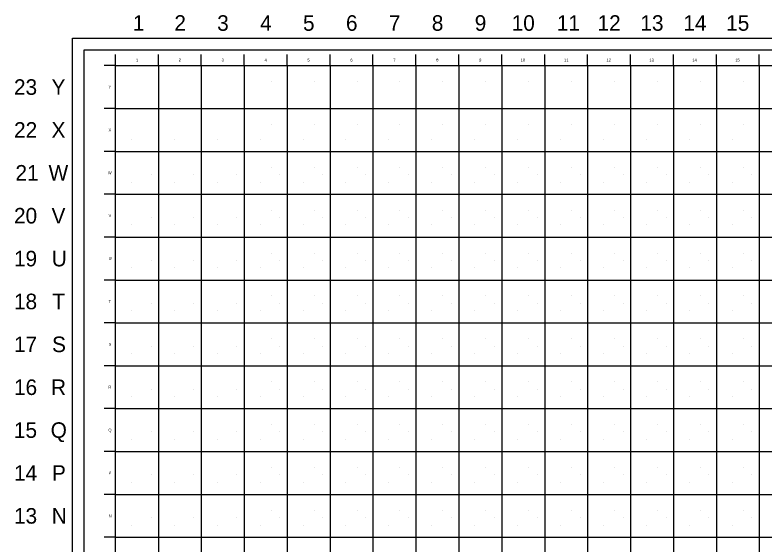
# Model space of a CAD drawing. Extents: x -0.05 to 1.19, y 0 to 0.86.
# Drawn here: x -0.047 to 0.565, y 0.428 to 0.86 of the extents above; entities that cross this region are included whole.
import ezdxf

# ---------------------------------------------------------------- set-up
doc = ezdxf.new("R2010")
doc.units = 0
for name, color, linetype in [('G-ANNO-NPLT', 7, 'Continuous'), ('G-ANNO-TEXT', 7, 'Continuous'), ('G-ANNO-TTLB', 7, 'Continuous'), ('G-ANNO-TTLB-GRID', 7, 'Continuous')]:
    doc.layers.add(name, color=color, linetype=linetype)

msp = doc.modelspace()

# ---------------------------------------------------------------- linework, layer by layer
at = {"layer": 'G-ANNO-NPLT'}
for p, q in [((0.16207, 0.80547), (0.16207, 0.80547)), ((0.19708, 0.80547), (0.19708, 0.80547)), ((0.23207, 0.80547), (0.23207, 0.80547)), ((0.26708, 0.80547), (0.26708, 0.80547)), ((0.30207, 0.80547), (0.30207, 0.80547)), ((0.33707, 0.80547), (0.33707, 0.80547)), ((0.37207, 0.80547), (0.37207, 0.80547)), ((0.40707, 0.80547), (0.40707, 0.80547)), ((0.44207, 0.80547), (0.44207, 0.80547)), ((0.47707, 0.80547), (0.47707, 0.80547)), ((0.51207, 0.80547), (0.51207, 0.80547)), ((0.54707, 0.80547), (0.54707, 0.80547)), ((0.16207, 0.77047), (0.16207, 0.77047)), ((0.19708, 0.77047), (0.19708, 0.77047)), ((0.23207, 0.77047), (0.23207, 0.77047)), ((0.26708, 0.77047), (0.26708, 0.77047)), ((0.30207, 0.77047), (0.30207, 0.77047)), ((0.33707, 0.77047), (0.33707, 0.77047)), ((0.37207, 0.77047), (0.37207, 0.77047)), ((0.40707, 0.77047), (0.40707, 0.77047)), ((0.44207, 0.77047), (0.44207, 0.77047)), ((0.47707, 0.77047), (0.47707, 0.77047)), ((0.51207, 0.77047), (0.51207, 0.77047)), ((0.54707, 0.77047), (0.54707, 0.77047)), ((0.04807, 0.75847), (0.04807, 0.75847)), ((0.08307, 0.75847), (0.08307, 0.75847)), ((0.11807, 0.75847), (0.11807, 0.75847)), ((0.15307, 0.75847), (0.15307, 0.75847)), ((0.18807, 0.75847), (0.18807, 0.75847)), ((0.22307, 0.75847), (0.22307, 0.75847)), ((0.25807, 0.75847), (0.25807, 0.75847)), ((0.29307, 0.75847), (0.29307, 0.75847)), ((0.32808, 0.75847), (0.32808, 0.75847)), ((0.36307, 0.75847), (0.36307, 0.75847)), ((0.39807, 0.75847), (0.39807, 0.75847)), ((0.43307, 0.75847), (0.43307, 0.75847)), ((0.46807, 0.75847), (0.46807, 0.75847)), ((0.50307, 0.75847), (0.50307, 0.75847)), ((0.53807, 0.75847), (0.53807, 0.75847)), ((0.16207, 0.73547), (0.16207, 0.73547)), ((0.19708, 0.73547), (0.19708, 0.73547)), ((0.23207, 0.73547), (0.23207, 0.73547)), ((0.26708, 0.73547), (0.26708, 0.73547)), ((0.30207, 0.73547), (0.30207, 0.73547)), ((0.33707, 0.73547), (0.33707, 0.73547)), ((0.37207, 0.73547), (0.37207, 0.73547)), ((0.40707, 0.73547), (0.40707, 0.73547)), ((0.44207, 0.73547), (0.44207, 0.73547)), ((0.47707, 0.73547), (0.47707, 0.73547)), ((0.51207, 0.73547), (0.51207, 0.73547)), ((0.54707, 0.73547), (0.54707, 0.73547)), ((0.06407, 0.72947), (0.06407, 0.72947)), ((0.09907, 0.72947), (0.09907, 0.72947)), ((0.13407, 0.72947), (0.13407, 0.72947)), ((0.16908, 0.72947), (0.16908, 0.72947)), ((0.20407, 0.72947), (0.20407, 0.72947)), ((0.23907, 0.72947), (0.23907, 0.72947)), ((0.27408, 0.72947), (0.27408, 0.72947)), ((0.30907, 0.72947), (0.30907, 0.72947)), ((0.34407, 0.72947), (0.34407, 0.72947)), ((0.37907, 0.72947), (0.37907, 0.72947)), ((0.41407, 0.72947), (0.41407, 0.72947)), ((0.44908, 0.72947), (0.44908, 0.72947)), ((0.48407, 0.72947), (0.48407, 0.72947)), ((0.51907, 0.72947), (0.51907, 0.72947)), ((0.55407, 0.72947), (0.55407, 0.72947)), ((0.04807, 0.72347), (0.04807, 0.72347)), ((0.08307, 0.72347), (0.08307, 0.72347)), ((0.11807, 0.72347), (0.11807, 0.72347)), ((0.15307, 0.72347), (0.15307, 0.72347)), ((0.18807, 0.72347), (0.18807, 0.72347)), ((0.22307, 0.72347), (0.22307, 0.72347)), ((0.25807, 0.72347), (0.25807, 0.72347)), ((0.29307, 0.72347), (0.29307, 0.72347)), ((0.32808, 0.72347), (0.32808, 0.72347)), ((0.36307, 0.72347), (0.36307, 0.72347)), ((0.39807, 0.72347), (0.39807, 0.72347)), ((0.43307, 0.72347), (0.43307, 0.72347)), ((0.46807, 0.72347), (0.46807, 0.72347)), ((0.50307, 0.72347), (0.50307, 0.72347)), ((0.53807, 0.72347), (0.53807, 0.72347)), ((0.16207, 0.70047), (0.16207, 0.70047)), ((0.19708, 0.70047), (0.19708, 0.70047)), ((0.23207, 0.70047), (0.23207, 0.70047)), ((0.26708, 0.70047), (0.26708, 0.70047)), ((0.30207, 0.70047), (0.30207, 0.70047)), ((0.33707, 0.70047), (0.33707, 0.70047)), ((0.37207, 0.70047), (0.37207, 0.70047)), ((0.40707, 0.70047), (0.40707, 0.70047)), ((0.44207, 0.70047), (0.44207, 0.70047)), ((0.47707, 0.70047), (0.47707, 0.70047)), ((0.51207, 0.70047), (0.51207, 0.70047)), ((0.54707, 0.70047), (0.54707, 0.70047)), ((0.06407, 0.69447), (0.06407, 0.69447)), ((0.09907, 0.69447), (0.09907, 0.69447)), ((0.13407, 0.69447), (0.13407, 0.69447)), ((0.16908, 0.69447), (0.16908, 0.69447)), ((0.20407, 0.69447), (0.20407, 0.69447)), ((0.23907, 0.69447), (0.23907, 0.69447)), ((0.27408, 0.69447), (0.27408, 0.69447)), ((0.30907, 0.69447), (0.30907, 0.69447)), ((0.34407, 0.69447), (0.34407, 0.69447)), ((0.37907, 0.69447), (0.37907, 0.69447)), ((0.41407, 0.69447), (0.41407, 0.69447)), ((0.44908, 0.69447), (0.44908, 0.69447)), ((0.48407, 0.69447), (0.48407, 0.69447)), ((0.51907, 0.69447), (0.51907, 0.69447)), ((0.55407, 0.69447), (0.55407, 0.69447)), ((0.04807, 0.68847), (0.04807, 0.68847)), ((0.08307, 0.68847), (0.08307, 0.68847)), ((0.11807, 0.68847), (0.11807, 0.68847)), ((0.15307, 0.68847), (0.15307, 0.68847)), ((0.18807, 0.68847), (0.18807, 0.68847)), ((0.22307, 0.68847), (0.22307, 0.68847)), ((0.25807, 0.68847), (0.25807, 0.68847)), ((0.29307, 0.68847), (0.29307, 0.68847)), ((0.32808, 0.68847), (0.32808, 0.68847)), ((0.36307, 0.68847), (0.36307, 0.68847)), ((0.39807, 0.68847), (0.39807, 0.68847)), ((0.43307, 0.68847), (0.43307, 0.68847)), ((0.46807, 0.68847), (0.46807, 0.68847)), ((0.50307, 0.68847), (0.50307, 0.68847)), ((0.53807, 0.68847), (0.53807, 0.68847)), ((0.16207, 0.66547), (0.16207, 0.66547)), ((0.19708, 0.66547), (0.19708, 0.66547)), ((0.23207, 0.66547), (0.23207, 0.66547)), ((0.26708, 0.66547), (0.26708, 0.66547)), ((0.30207, 0.66547), (0.30207, 0.66547)), ((0.33707, 0.66547), (0.33707, 0.66547)), ((0.37207, 0.66547), (0.37207, 0.66547)), ((0.40707, 0.66547), (0.40707, 0.66547)), ((0.44207, 0.66547), (0.44207, 0.66547)), ((0.47707, 0.66547), (0.47707, 0.66547)), ((0.51207, 0.66547), (0.51207, 0.66547)), ((0.54707, 0.66547), (0.54707, 0.66547)), ((0.06407, 0.65947), (0.06407, 0.65947)), ((0.09907, 0.65947), (0.09907, 0.65947)), ((0.13407, 0.65947), (0.13407, 0.65947)), ((0.16908, 0.65947), (0.16908, 0.65947)), ((0.20407, 0.65947), (0.20407, 0.65947)), ((0.23907, 0.65947), (0.23907, 0.65947)), ((0.27408, 0.65947), (0.27408, 0.65947)), ((0.30907, 0.65947), (0.30907, 0.65947)), ((0.34407, 0.65947), (0.34407, 0.65947)), ((0.37907, 0.65947), (0.37907, 0.65947)), ((0.41407, 0.65947), (0.41407, 0.65947)), ((0.44908, 0.65947), (0.44908, 0.65947)), ((0.48407, 0.65947), (0.48407, 0.65947)), ((0.51907, 0.65947), (0.51907, 0.65947)), ((0.55407, 0.65947), (0.55407, 0.65947)), ((0.04807, 0.65347), (0.04807, 0.65347)), ((0.08307, 0.65347), (0.08307, 0.65347)), ((0.11807, 0.65347), (0.11807, 0.65347)), ((0.15307, 0.65347), (0.15307, 0.65347)), ((0.18807, 0.65347), (0.18807, 0.65347)), ((0.22307, 0.65347), (0.22307, 0.65347)), ((0.25807, 0.65347), (0.25807, 0.65347)), ((0.29307, 0.65347), (0.29307, 0.65347)), ((0.32808, 0.65347), (0.32808, 0.65347)), ((0.36307, 0.65347), (0.36307, 0.65347)), ((0.39807, 0.65347), (0.39807, 0.65347)), ((0.43307, 0.65347), (0.43307, 0.65347)), ((0.46807, 0.65347), (0.46807, 0.65347)), ((0.50307, 0.65347), (0.50307, 0.65347)), ((0.53807, 0.65347), (0.53807, 0.65347)), ((0.16207, 0.63047), (0.16207, 0.63047)), ((0.19708, 0.63047), (0.19708, 0.63047)), ((0.23207, 0.63047), (0.23207, 0.63047)), ((0.26708, 0.63047), (0.26708, 0.63047)), ((0.30207, 0.63047), (0.30207, 0.63047)), ((0.33707, 0.63047), (0.33707, 0.63047)), ((0.37207, 0.63047), (0.37207, 0.63047)), ((0.40707, 0.63047), (0.40707, 0.63047)), ((0.44207, 0.63047), (0.44207, 0.63047)), ((0.47707, 0.63047), (0.47707, 0.63047)), ((0.51207, 0.63047), (0.51207, 0.63047)), ((0.54707, 0.63047), (0.54707, 0.63047)), ((0.06407, 0.62447), (0.06407, 0.62447)), ((0.09907, 0.62447), (0.09907, 0.62447)), ((0.13407, 0.62447), (0.13407, 0.62447)), ((0.16908, 0.62447), (0.16908, 0.62447)), ((0.20407, 0.62447), (0.20407, 0.62447)), ((0.23907, 0.62447), (0.23907, 0.62447)), ((0.27408, 0.62447), (0.27408, 0.62447)), ((0.30907, 0.62447), (0.30907, 0.62447)), ((0.34407, 0.62447), (0.34407, 0.62447)), ((0.37907, 0.62447), (0.37907, 0.62447)), ((0.41407, 0.62447), (0.41407, 0.62447)), ((0.44908, 0.62447), (0.44908, 0.62447)), ((0.48407, 0.62447), (0.48407, 0.62447)), ((0.51907, 0.62447), (0.51907, 0.62447)), ((0.55407, 0.62447), (0.55407, 0.62447)), ((0.04807, 0.61847), (0.04807, 0.61847)), ((0.08307, 0.61847), (0.08307, 0.61847)), ((0.11807, 0.61847), (0.11807, 0.61847)), ((0.15307, 0.61847), (0.15307, 0.61847)), ((0.18807, 0.61847), (0.18807, 0.61847)), ((0.22307, 0.61847), (0.22307, 0.61847)), ((0.25807, 0.61847), (0.25807, 0.61847)), ((0.29307, 0.61847), (0.29307, 0.61847)), ((0.32808, 0.61847), (0.32808, 0.61847)), ((0.36307, 0.61847), (0.36307, 0.61847)), ((0.39807, 0.61847), (0.39807, 0.61847)), ((0.43307, 0.61847), (0.43307, 0.61847)), ((0.46807, 0.61847), (0.46807, 0.61847)), ((0.50307, 0.61847), (0.50307, 0.61847)), ((0.53807, 0.61847), (0.53807, 0.61847)), ((0.16207, 0.59547), (0.16207, 0.59547)), ((0.19708, 0.59547), (0.19708, 0.59547)), ((0.23207, 0.59547), (0.23207, 0.59547)), ((0.26708, 0.59547), (0.26708, 0.59547)), ((0.30207, 0.59547), (0.30207, 0.59547)), ((0.33707, 0.59547), (0.33707, 0.59547)), ((0.37207, 0.59547), (0.37207, 0.59547)), ((0.40707, 0.59547), (0.40707, 0.59547)), ((0.44207, 0.59547), (0.44207, 0.59547)), ((0.47707, 0.59547), (0.47707, 0.59547)), ((0.51207, 0.59547), (0.51207, 0.59547)), ((0.54707, 0.59547), (0.54707, 0.59547)), ((0.06407, 0.58947), (0.06407, 0.58947)), ((0.09907, 0.58947), (0.09907, 0.58947)), ((0.13407, 0.58947), (0.13407, 0.58947)), ((0.16908, 0.58947), (0.16908, 0.58947)), ((0.20407, 0.58947), (0.20407, 0.58947)), ((0.23907, 0.58947), (0.23907, 0.58947)), ((0.27408, 0.58947), (0.27408, 0.58947)), ((0.30907, 0.58947), (0.30907, 0.58947)), ((0.34407, 0.58947), (0.34407, 0.58947)), ((0.37907, 0.58947), (0.37907, 0.58947)), ((0.41407, 0.58947), (0.41407, 0.58947)), ((0.44908, 0.58947), (0.44908, 0.58947)), ((0.48407, 0.58947), (0.48407, 0.58947)), ((0.51907, 0.58947), (0.51907, 0.58947)), ((0.55407, 0.58947), (0.55407, 0.58947)), ((0.04807, 0.58347), (0.04807, 0.58347)), ((0.08307, 0.58347), (0.08307, 0.58347)), ((0.11807, 0.58347), (0.11807, 0.58347)), ((0.15307, 0.58347), (0.15307, 0.58347)), ((0.18807, 0.58347), (0.18807, 0.58347)), ((0.22307, 0.58347), (0.22307, 0.58347)), ((0.25807, 0.58347), (0.25807, 0.58347)), ((0.29307, 0.58347), (0.29307, 0.58347)), ((0.32808, 0.58347), (0.32808, 0.58347)), ((0.36307, 0.58347), (0.36307, 0.58347)), ((0.39807, 0.58347), (0.39807, 0.58347)), ((0.43307, 0.58347), (0.43307, 0.58347)), ((0.46807, 0.58347), (0.46807, 0.58347)), ((0.50307, 0.58347), (0.50307, 0.58347)), ((0.53807, 0.58347), (0.53807, 0.58347)), ((0.16207, 0.56047), (0.16207, 0.56047)), ((0.19708, 0.56047), (0.19708, 0.56047)), ((0.23207, 0.56047), (0.23207, 0.56047)), ((0.26708, 0.56047), (0.26708, 0.56047)), ((0.30207, 0.56047), (0.30207, 0.56047)), ((0.33707, 0.56047), (0.33707, 0.56047)), ((0.37207, 0.56047), (0.37207, 0.56047)), ((0.40707, 0.56047), (0.40707, 0.56047)), ((0.44207, 0.56047), (0.44207, 0.56047)), ((0.47707, 0.56047), (0.47707, 0.56047)), ((0.51207, 0.56047), (0.51207, 0.56047)), ((0.54707, 0.56047), (0.54707, 0.56047)), ((0.06407, 0.55447), (0.06407, 0.55447)), ((0.09907, 0.55447), (0.09907, 0.55447)), ((0.13407, 0.55447), (0.13407, 0.55447)), ((0.16908, 0.55447), (0.16908, 0.55447)), ((0.20407, 0.55447), (0.20407, 0.55447)), ((0.23907, 0.55447), (0.23907, 0.55447)), ((0.27408, 0.55447), (0.27408, 0.55447)), ((0.30907, 0.55447), (0.30907, 0.55447)), ((0.34407, 0.55447), (0.34407, 0.55447)), ((0.37907, 0.55447), (0.37907, 0.55447)), ((0.41407, 0.55447), (0.41407, 0.55447)), ((0.44908, 0.55447), (0.44908, 0.55447)), ((0.48407, 0.55447), (0.48407, 0.55447)), ((0.51907, 0.55447), (0.51907, 0.55447)), ((0.55407, 0.55447), (0.55407, 0.55447)), ((0.04807, 0.54847), (0.04807, 0.54847)), ((0.08307, 0.54847), (0.08307, 0.54847)), ((0.11807, 0.54847), (0.11807, 0.54847)), ((0.15307, 0.54847), (0.15307, 0.54847)), ((0.18807, 0.54847), (0.18807, 0.54847)), ((0.22307, 0.54847), (0.22307, 0.54847)), ((0.25807, 0.54847), (0.25807, 0.54847)), ((0.29307, 0.54847), (0.29307, 0.54847)), ((0.32808, 0.54847), (0.32808, 0.54847)), ((0.36307, 0.54847), (0.36307, 0.54847)), ((0.39807, 0.54847), (0.39807, 0.54847)), ((0.43307, 0.54847), (0.43307, 0.54847)), ((0.46807, 0.54847), (0.46807, 0.54847)), ((0.50307, 0.54847), (0.50307, 0.54847)), ((0.53807, 0.54847), (0.53807, 0.54847)), ((0.16207, 0.52547), (0.16207, 0.52547)), ((0.19708, 0.52547), (0.19708, 0.52547)), ((0.23207, 0.52547), (0.23207, 0.52547)), ((0.26708, 0.52547), (0.26708, 0.52547)), ((0.30207, 0.52547), (0.30207, 0.52547)), ((0.33707, 0.52547), (0.33707, 0.52547)), ((0.37207, 0.52547), (0.37207, 0.52547)), ((0.40707, 0.52547), (0.40707, 0.52547)), ((0.44207, 0.52547), (0.44207, 0.52547)), ((0.47707, 0.52547), (0.47707, 0.52547)), ((0.51207, 0.52547), (0.51207, 0.52547)), ((0.54707, 0.52547), (0.54707, 0.52547)), ((0.06407, 0.51947), (0.06407, 0.51947)), ((0.09907, 0.51947), (0.09907, 0.51947)), ((0.13407, 0.51947), (0.13407, 0.51947)), ((0.16908, 0.51947), (0.16908, 0.51947)), ((0.20407, 0.51947), (0.20407, 0.51947)), ((0.23907, 0.51947), (0.23907, 0.51947)), ((0.27408, 0.51947), (0.27408, 0.51947)), ((0.30907, 0.51947), (0.30907, 0.51947)), ((0.34407, 0.51947), (0.34407, 0.51947)), ((0.37907, 0.51947), (0.37907, 0.51947)), ((0.41407, 0.51947), (0.41407, 0.51947)), ((0.44908, 0.51947), (0.44908, 0.51947)), ((0.48407, 0.51947), (0.48407, 0.51947)), ((0.51907, 0.51947), (0.51907, 0.51947)), ((0.55407, 0.51947), (0.55407, 0.51947)), ((0.04807, 0.51347), (0.04807, 0.51347)), ((0.08307, 0.51347), (0.08307, 0.51347)), ((0.11807, 0.51347), (0.11807, 0.51347)), ((0.15307, 0.51347), (0.15307, 0.51347)), ((0.18807, 0.51347), (0.18807, 0.51347)), ((0.22307, 0.51347), (0.22307, 0.51347)), ((0.25807, 0.51347), (0.25807, 0.51347)), ((0.29307, 0.51347), (0.29307, 0.51347)), ((0.32808, 0.51347), (0.32808, 0.51347)), ((0.36307, 0.51347), (0.36307, 0.51347)), ((0.39807, 0.51347), (0.39807, 0.51347)), ((0.43307, 0.51347), (0.43307, 0.51347)), ((0.46807, 0.51347), (0.46807, 0.51347)), ((0.50307, 0.51347), (0.50307, 0.51347)), ((0.53807, 0.51347), (0.53807, 0.51347)), ((0.16207, 0.49047), (0.16207, 0.49047)), ((0.19708, 0.49047), (0.19708, 0.49047)), ((0.23207, 0.49047), (0.23207, 0.49047)), ((0.26708, 0.49047), (0.26708, 0.49047)), ((0.30207, 0.49047), (0.30207, 0.49047)), ((0.33707, 0.49047), (0.33707, 0.49047)), ((0.37207, 0.49047), (0.37207, 0.49047)), ((0.40707, 0.49047), (0.40707, 0.49047)), ((0.44207, 0.49047), (0.44207, 0.49047)), ((0.47707, 0.49047), (0.47707, 0.49047)), ((0.51207, 0.49047), (0.51207, 0.49047)), ((0.54707, 0.49047), (0.54707, 0.49047)), ((0.06407, 0.48447), (0.06407, 0.48447)), ((0.09907, 0.48447), (0.09907, 0.48447)), ((0.13407, 0.48447), (0.13407, 0.48447)), ((0.16908, 0.48447), (0.16908, 0.48447)), ((0.20407, 0.48447), (0.20407, 0.48447)), ((0.23907, 0.48447), (0.23907, 0.48447)), ((0.27408, 0.48447), (0.27408, 0.48447)), ((0.30907, 0.48447), (0.30907, 0.48447)), ((0.34407, 0.48447), (0.34407, 0.48447)), ((0.37907, 0.48447), (0.37907, 0.48447)), ((0.41407, 0.48447), (0.41407, 0.48447)), ((0.44908, 0.48447), (0.44908, 0.48447)), ((0.48407, 0.48447), (0.48407, 0.48447)), ((0.51907, 0.48447), (0.51907, 0.48447)), ((0.55407, 0.48447), (0.55407, 0.48447)), ((0.04807, 0.47847), (0.04807, 0.47847)), ((0.08307, 0.47847), (0.08307, 0.47847)), ((0.11807, 0.47847), (0.11807, 0.47847)), ((0.15307, 0.47847), (0.15307, 0.47847)), ((0.18807, 0.47847), (0.18807, 0.47847)), ((0.22307, 0.47847), (0.22307, 0.47847)), ((0.25807, 0.47847), (0.25807, 0.47847)), ((0.29307, 0.47847), (0.29307, 0.47847)), ((0.32808, 0.47847), (0.32808, 0.47847)), ((0.36307, 0.47847), (0.36307, 0.47847)), ((0.39807, 0.47847), (0.39807, 0.47847)), ((0.43307, 0.47847), (0.43307, 0.47847)), ((0.46807, 0.47847), (0.46807, 0.47847)), ((0.50307, 0.47847), (0.50307, 0.47847)), ((0.53807, 0.47847), (0.53807, 0.47847)), ((0.16207, 0.45547), (0.16207, 0.45547)), ((0.19708, 0.45547), (0.19708, 0.45547)), ((0.23207, 0.45547), (0.23207, 0.45547)), ((0.26708, 0.45547), (0.26708, 0.45547)), ((0.30207, 0.45547), (0.30207, 0.45547)), ((0.33707, 0.45547), (0.33707, 0.45547)), ((0.37207, 0.45547), (0.37207, 0.45547)), ((0.40707, 0.45547), (0.40707, 0.45547)), ((0.44207, 0.45547), (0.44207, 0.45547)), ((0.47707, 0.45547), (0.47707, 0.45547)), ((0.51207, 0.45547), (0.51207, 0.45547)), ((0.54707, 0.45547), (0.54707, 0.45547)), ((0.06407, 0.44947), (0.06407, 0.44947)), ((0.09907, 0.44947), (0.09907, 0.44947)), ((0.13407, 0.44947), (0.13407, 0.44947)), ((0.16908, 0.44947), (0.16908, 0.44947)), ((0.20407, 0.44947), (0.20407, 0.44947)), ((0.23907, 0.44947), (0.23907, 0.44947)), ((0.27408, 0.44947), (0.27408, 0.44947)), ((0.30907, 0.44947), (0.30907, 0.44947)), ((0.34407, 0.44947), (0.34407, 0.44947)), ((0.37907, 0.44947), (0.37907, 0.44947)), ((0.41407, 0.44947), (0.41407, 0.44947)), ((0.44908, 0.44947), (0.44908, 0.44947)), ((0.48407, 0.44947), (0.48407, 0.44947)), ((0.51907, 0.44947), (0.51907, 0.44947)), ((0.55407, 0.44947), (0.55407, 0.44947)), ((0.04807, 0.44347), (0.04807, 0.44347)), ((0.08307, 0.44347), (0.08307, 0.44347)), ((0.11807, 0.44347), (0.11807, 0.44347)), ((0.15307, 0.44347), (0.15307, 0.44347)), ((0.18807, 0.44347), (0.18807, 0.44347)), ((0.22307, 0.44347), (0.22307, 0.44347)), ((0.25807, 0.44347), (0.25807, 0.44347)), ((0.29307, 0.44347), (0.29307, 0.44347)), ((0.32808, 0.44347), (0.32808, 0.44347)), ((0.36307, 0.44347), (0.36307, 0.44347)), ((0.39807, 0.44347), (0.39807, 0.44347)), ((0.43307, 0.44347), (0.43307, 0.44347)), ((0.46807, 0.44347), (0.46807, 0.44347)), ((0.50307, 0.44347), (0.50307, 0.44347)), ((0.53807, 0.44347), (0.53807, 0.44347))]:
    msp.add_line(p, q, dxfattribs=at)
msp.add_lwpolyline([(0.00952, 0.83147), (1.17948, 0.83147), (1.17948, 0.00952), (0.00952, 0.00952)], close=True, dxfattribs=at)
at = {"layer": 'G-ANNO-TEXT'}
for p, q in [((0.03507, 0.81847), (0.03507, 0.82753)), ((0.07007, 0.81847), (0.07007, 0.82753)), ((0.10508, 0.81847), (0.10508, 0.82753)), ((0.14008, 0.81847), (0.14008, 0.82753)), ((0.17507, 0.81847), (0.17507, 0.82753)), ((0.21007, 0.81847), (0.21007, 0.82753)), ((0.24507, 0.81847), (0.24507, 0.82753)), ((0.28007, 0.81847), (0.28007, 0.82753)), ((0.31507, 0.81847), (0.31507, 0.82753)), ((0.35007, 0.81847), (0.35007, 0.82753)), ((0.38508, 0.81847), (0.38508, 0.82753)), ((0.42007, 0.81847), (0.42007, 0.82753)), ((0.45507, 0.81847), (0.45507, 0.82753)), ((0.49007, 0.81847), (0.49007, 0.82753)), ((0.52507, 0.81847), (0.52507, 0.82753)), ((0.56007, 0.81847), (0.56007, 0.82753)), ((0.03507, 0.81847), (0.02601, 0.81847)), ((0.03507, 0.78347), (0.02601, 0.78347)), ((0.03507, 0.74847), (0.02601, 0.74847)), ((0.03507, 0.71347), (0.02601, 0.71347)), ((0.03507, 0.67847), (0.02601, 0.67847)), ((0.03507, 0.64347), (0.02601, 0.64347)), ((0.03507, 0.60847), (0.02601, 0.60847)), ((0.03507, 0.57347), (0.02601, 0.57347)), ((0.03507, 0.53847), (0.02601, 0.53847)), ((0.03507, 0.50347), (0.02601, 0.50347)), ((0.03507, 0.46847), (0.02601, 0.46847)), ((0.03507, 0.43347), (0.02601, 0.43347))]:
    msp.add_line(p, q, dxfattribs=at)
at = {"layer": 'G-ANNO-TTLB'}
for points in [[(0, 0.841), (1.189, 0.841), (1.189, 0), (0, 0)], [(0.03507, 0.81847), (1.17009, 0.81847), (1.17009, 0.01347), (0.03507, 0.01347)]]:
    msp.add_lwpolyline(points, close=True, dxfattribs=at)
at = {"layer": 'G-ANNO-TTLB-GRID'}
for p, q in [((0.07007, 0.81847), (0.07007, 0.01347)), ((0.10508, 0.81847), (0.10508, 0.01347)), ((0.14008, 0.81847), (0.14008, 0.01347)), ((0.17507, 0.81847), (0.17507, 0.01347)), ((0.21007, 0.81847), (0.21007, 0.01347)), ((0.24507, 0.81847), (0.24507, 0.01347)), ((0.28007, 0.81847), (0.28007, 0.01347)), ((0.31507, 0.81847), (0.31507, 0.01347)), ((0.35007, 0.81847), (0.35007, 0.01347)), ((0.38508, 0.81847), (0.38508, 0.01347)), ((0.42007, 0.81847), (0.42007, 0.01347)), ((0.45507, 0.81847), (0.45507, 0.01347)), ((0.49007, 0.81847), (0.49007, 0.01347)), ((0.52507, 0.81847), (0.52507, 0.01347)), ((0.56007, 0.81847), (0.56007, 0.01347)), ((0.03507, 0.78347), (1.17009, 0.78347)), ((0.03507, 0.74847), (1.17009, 0.74847)), ((0.03507, 0.71347), (1.17009, 0.71347)), ((0.03507, 0.67847), (1.17009, 0.67847)), ((0.03507, 0.64347), (1.17009, 0.64347)), ((0.03507, 0.60847), (1.17009, 0.60847)), ((0.03507, 0.57347), (1.12007, 0.57347)), ((0.03507, 0.53847), (1.12007, 0.53847)), ((0.03507, 0.50347), (1.12007, 0.50347)), ((0.03507, 0.46847), (1.12007, 0.46847)), ((0.03507, 0.43347), (1.12007, 0.43347))]:
    msp.add_line(p, q, dxfattribs=at)

# ---------------------------------------------------------------- texts
at = {"layer": 'G-ANNO-NPLT'}
for s, p in [('1', (0.04927, 0.8469)), ('2', (0.08311, 0.8469)), ('3', (0.11804, 0.8469)), ('4', (0.15307, 0.8469)), ('5', (0.188, 0.8469)), ('6', (0.22304, 0.8469)), ('7', (0.25804, 0.8469)), ('8', (0.29304, 0.8469)), ('9', (0.32804, 0.8469)), ('10', (0.35814, 0.8469)), ('11', (0.395, 0.8469)), ('12', (0.42818, 0.8469)), ('13', (0.46311, 0.8469)), ('14', (0.49814, 0.8469)), ('15', (0.53306, 0.8469)), ('23', (-0.04768, 0.79462)), ('Y', (-0.01703, 0.79462)), ('22', (-0.04762, 0.75962)), ('X', (-0.01704, 0.75962)), ('21', (-0.04646, 0.72462)), ('W', (-0.01945, 0.72462)), ('20', (-0.04766, 0.68962)), ('V', (-0.01702, 0.68962)), ('19', (-0.04769, 0.65462)), ('U', (-0.01687, 0.65462)), ('18', (-0.04769, 0.61962)), ('T', (-0.01642, 0.61962)), ('17', (-0.04768, 0.58462)), ('S', (-0.01663, 0.58462)), ('16', (-0.04768, 0.54962)), ('R', (-0.01746, 0.54962)), ('15', (-0.04773, 0.51462)), ('Q', (-0.01775, 0.51462)), ('14', (-0.04766, 0.47962)), ('P', (-0.01671, 0.47962)), ('13', (-0.04768, 0.44462)), ('N', (-0.01686, 0.44462))]:
    msp.add_text(s, height=0.0127, dxfattribs=at).set_placement(p)
at = {"layer": 'G-ANNO-TEXT'}
for s, p in [('1', (0.05192, 0.8218)), ('2', (0.08665, 0.8218)), ('3', (0.12163, 0.8218)), ('4', (0.15664, 0.8218)), ('5', (0.19162, 0.8218)), ('6', (0.22663, 0.8218)), ('7', (0.26163, 0.8218)), ('8', (0.29663, 0.8218)), ('9', (0.33163, 0.8218)), ('10', (0.36547, 0.8218)), ('11', (0.40091, 0.8218)), ('12', (0.43548, 0.8218)), ('13', (0.47047, 0.8218)), ('14', (0.50548, 0.8218)), ('15', (0.54046, 0.8218)), ('Y', (0.02944, 0.79977)), ('X', (0.02944, 0.76477)), ('W', (0.02887, 0.72977)), ('V', (0.02944, 0.69477)), ('U', (0.02948, 0.65977)), ('T', (0.02958, 0.62477)), ('S', (0.02953, 0.58977)), ('R', (0.02933, 0.55477)), ('Q', (0.02927, 0.51977)), ('P', (0.02951, 0.48477)), ('N', (0.02948, 0.44977))]:
    msp.add_text(s, height=0.0024, dxfattribs=at).set_placement(p)

doc.saveas('drawing.dxf')
